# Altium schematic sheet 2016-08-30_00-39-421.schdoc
size 247 x 144 mm; SheetNumber: 1; SheetTotal: 1
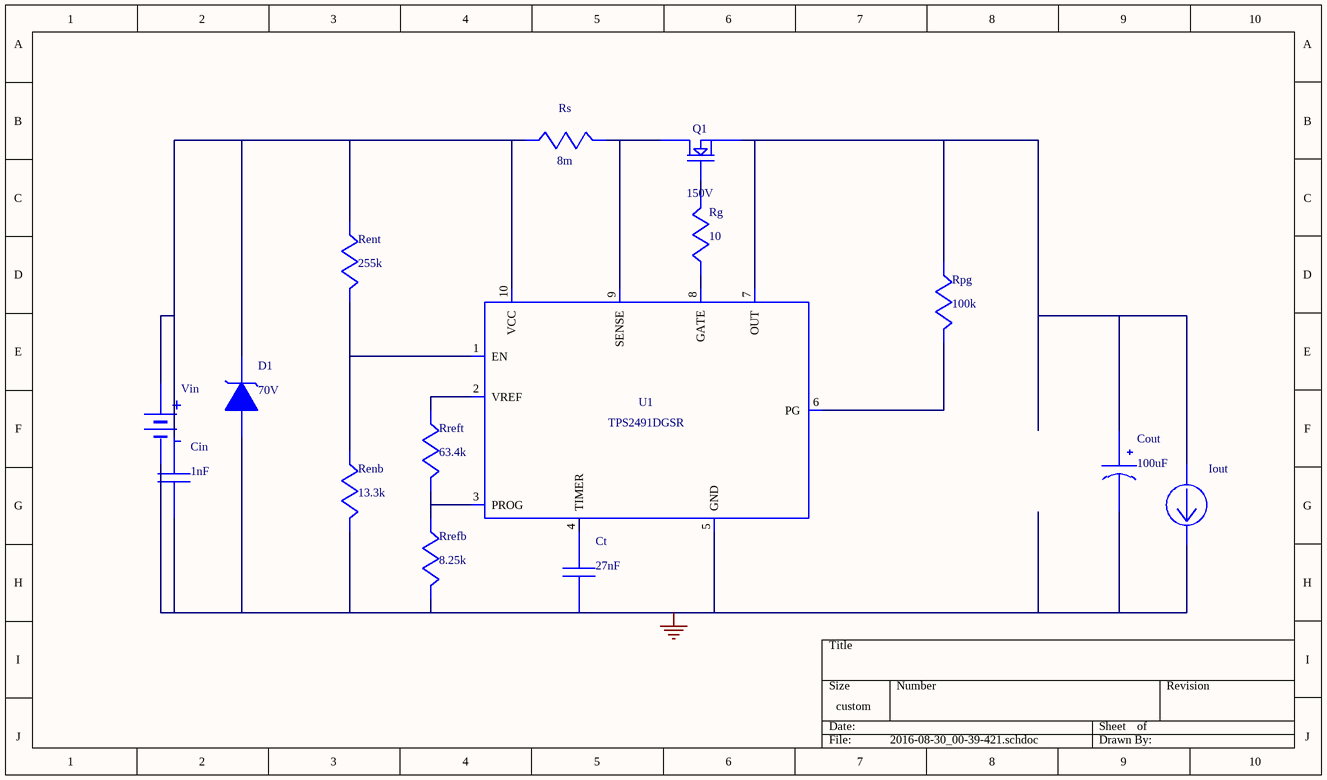
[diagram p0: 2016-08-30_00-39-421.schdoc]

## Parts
Cin  value 1nF  (hidden comment: GRM155R72A102KA01D)
Cout  value 100uF  (hidden comment: EEV-FK1K101Q)
Ct  value 27nF  (hidden comment: GRM155R61C273KA01D)
D1  value 70V  (hidden comment: 5.0SMDJ70A)
Iout  WB_CURRENT_LOAD  (value not drawn)
Q1  value 150V  (hidden comment: BSC190N15NS3 G)
Renb  value 13.3k  (hidden comment: ERJ-6ENF1332V)
Rent  value 255k  (hidden comment: ERJ-6ENF2553V)
Rg  value 10  (hidden comment: CRCW080510R0FKEA)
Rpg  value 100k  (hidden comment: ERJ-6ENF1003V)
Rrefb  value 8.25k  (hidden comment: ERJ-6ENF8251V)
Rreft  value 63.4k  (hidden comment: ERJ-6ENF6342V)
Rs  value 8m  (hidden comment: PRL1632-R008-F-T1)
U1  TPS2491DGSR
Vin  WB_BATTERY  (value not drawn)

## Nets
0: Cin.2 Cout.2(-) Ct.2 D1.2(A) Iout.2(-) Renb.1 Rrefb.1 U1.5(GND) Vin.2(-)
NetCin_1: Cin.1 D1.1(K) Rent.2 Rs.2 U1.10(VCC) Vin.1(+)
NetCout_1: Cout.1(+) Iout.1(+) Q1.1(Source) Q1.2(Source) Q1.3(Source) Rpg.2 U1.7(OUT)
NetCt_1: Ct.1 U1.4(TIMER)
NetQ1_4: Q1.4(Gate) Rg.1
NetQ1_5: Q1.5(Drain) Q1.6(Drain) Q1.7(Drain) Q1.8(Drain) Q1.9(Drain) Rs.1 U1.9(SENSE)
NetRenb_2: Renb.2 Rent.1 U1.1(EN)
NetRg_2: Rg.2 U1.8(GATE)
NetRpg_1: Rpg.1 U1.6(PG)
NetRrefb_2: Rrefb.2 Rreft.1 U1.3(PROG)
NetRreft_2: Rreft.2 U1.2(VREF)

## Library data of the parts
Cin = GRM155R72A102KA01D: GRM155R72A102KA0; Manufacturer Name: MuRata
Cout = EEV-FK1K101Q: Manufacturer Name: Panasonic
Ct = GRM155R61C273KA01D: GRM155R61C273KA0; Manufacturer Name: MuRata
D1 = 5.0SMDJ70A: Manufacturer Name: Littelfuse
Q1 = BSC190N15NS3 G: Manufacturer Name: Infineon Technologies
Renb = ERJ-6ENF1332V: Manufacturer Name: Panasonic
Rent = ERJ-6ENF2553V: Manufacturer Name: Panasonic
Rg = CRCW080510R0FKEA: Manufacturer Name: Vishay-Dale
Rpg = ERJ-6ENF1003V: Manufacturer Name: Panasonic
Rrefb = ERJ-6ENF8251V: Manufacturer Name: Panasonic
Rreft = ERJ-6ENF6342V: Manufacturer Name: Panasonic
Rs = PRL1632-R008-F-T1: PRL1632-R008-F-T; Manufacturer Name: Susumu Co Ltd
U1 = TPS2491DGSR: Manufacturer Name: Texas Instruments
